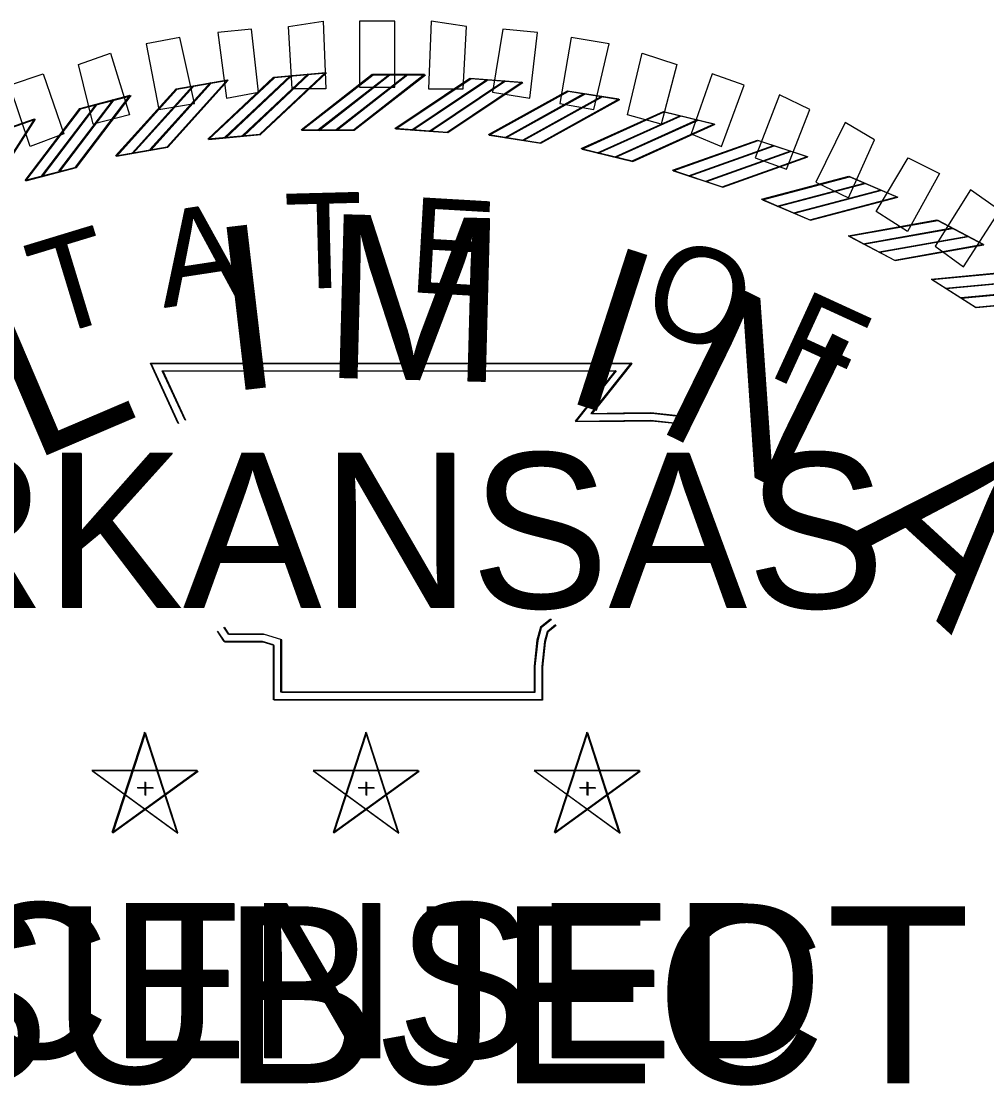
# Model space of a CAD drawing. Extents: x 16 to 1228740, y 11 to 152440.
# Drawn here: x 17.7404 to 17.8102, y 10.9139 to 10.9908 of the extents above; entities that cross this region are included whole.
import ezdxf

# ---------------------------------------------------------------- set-up
doc = ezdxf.new("R2010")
doc.units = 0
for name, color, linetype in [('STAMP_FRED', 7, 'Continuous'), ('STAMP_HUSSAM', 7, 'Continuous'), ('STAMP_JUSTIN', 7, 'Continuous'), ('STAMP_PRELIM', 7, 'Continuous')]:
    doc.layers.add(name, color=color, linetype=linetype)

msp = doc.modelspace()

# ---------------------------------------------------------------- linework, layer by layer
at = {"layer": 'STAMP_FRED'}
for p, q in [((17.758689, 10.986711), (17.762443, 10.987057)), ((17.765828, 10.986922), (17.769598, 10.986922)), ((17.77289, 10.986639), (17.776649, 10.986362)), ((17.751633, 10.985868), (17.755345, 10.986523)), ((17.74467, 10.984445), (17.748316, 10.985404)), ((17.779937, 10.985724), (17.783661, 10.985138)), ((17.737849, 10.982452), (17.741403, 10.983709)), ((17.786885, 10.98423), (17.790548, 10.983338)), ((17.760683, 10.98291), (17.764462, 10.98291)), ((17.767464, 10.983016), (17.771233, 10.982738)), ((17.753934, 10.982244), (17.757697, 10.982591)), ((17.774231, 10.982561), (17.777964, 10.981973)), ((17.793685, 10.982168), (17.797262, 10.980976)), ((17.747263, 10.981024), (17.750984, 10.98168)), ((17.780937, 10.981549), (17.784609, 10.980655)), ((17.740715, 10.979257), (17.74437, 10.980218)), ((17.787537, 10.979987), (17.791122, 10.978793)), ((17.800292, 10.97955), (17.803759, 10.978068)), ((17.793985, 10.977885), (17.797459, 10.976399)), ((17.806661, 10.976397), (17.809993, 10.974633)), ((17.800237, 10.975258), (17.803577, 10.97349)), ((17.806251, 10.972124), (17.809434, 10.970086)), ((17.749354, 10.939355), (17.746995, 10.932119)), ((17.751704, 10.932123), (17.749359, 10.939363)), ((17.765345, 10.939355), (17.762986, 10.932119)), ((17.767695, 10.932123), (17.76535, 10.939363)), ((17.781336, 10.939355), (17.778977, 10.932119)), ((17.783686, 10.932123), (17.781341, 10.939363)), ((17.753156, 10.936593), (17.745545, 10.9366)), ((17.745552, 10.936593), (17.751705, 10.932113)), ((17.747004, 10.932123), (17.753165, 10.936591)), ((17.769147, 10.936593), (17.761536, 10.9366)), ((17.761543, 10.936593), (17.767696, 10.932113)), ((17.762995, 10.932123), (17.769157, 10.936591)), ((17.785138, 10.936593), (17.777527, 10.9366)), ((17.777534, 10.936593), (17.783687, 10.932113)), ((17.778986, 10.932123), (17.785148, 10.936591)), ((17.748812, 10.935377), (17.749943, 10.935377)), ((17.749361, 10.935783), (17.749361, 10.934828)), ((17.764803, 10.935377), (17.765934, 10.935377)), ((17.765352, 10.935783), (17.765352, 10.934828)), ((17.780794, 10.935377), (17.781926, 10.935377)), ((17.781343, 10.935783), (17.781343, 10.934828))]:
    msp.add_line(p, q, dxfattribs=at)
for points in [[(17.75393, 10.982241), (17.758684, 10.986707)], [(17.755139, 10.982341), (17.759893, 10.986807)], [(17.756441, 10.98249), (17.761195, 10.986956)], [(17.757692, 10.982593), (17.762446, 10.98706)], [(17.760679, 10.982906), (17.765823, 10.986918)], [(17.761892, 10.982895), (17.767036, 10.986907)], [(17.763202, 10.982924), (17.768346, 10.986936)], [(17.764458, 10.982913), (17.769601, 10.986924)], [(17.76746, 10.983012), (17.772884, 10.986636)], [(17.747259, 10.98102), (17.751628, 10.985864)], [(17.748456, 10.98122), (17.752825, 10.986064)], [(17.749741, 10.981475), (17.754109, 10.986319)], [(17.750979, 10.981682), (17.755348, 10.986526)], [(17.768669, 10.982912), (17.774093, 10.986535)], [(17.769977, 10.982845), (17.775401, 10.986468)], [(17.771229, 10.982741), (17.776653, 10.986365)], [(17.743147, 10.979911), (17.747101, 10.9851)], [(17.744365, 10.98022), (17.748319, 10.985408)], [(17.774226, 10.982558), (17.779931, 10.985721)], [(17.775423, 10.982358), (17.781128, 10.985521)], [(17.776721, 10.982183), (17.782426, 10.985346)], [(17.77796, 10.981977), (17.783665, 10.98514)], [(17.740712, 10.979252), (17.744666, 10.984441)], [(17.741888, 10.97955), (17.745842, 10.984738)], [(17.737893, 10.978216), (17.741405, 10.983713)], [(17.780932, 10.981547), (17.786879, 10.984228)], [(17.782108, 10.981249), (17.788055, 10.98393)], [(17.783387, 10.980967), (17.789334, 10.983648)], [(17.784605, 10.980659), (17.790552, 10.98334)], [(17.787531, 10.979985), (17.793679, 10.982166)], [(17.788679, 10.979591), (17.794827, 10.981772)], [(17.789931, 10.979205), (17.796078, 10.981386)], [(17.791118, 10.978797), (17.797266, 10.980978)], [(17.793979, 10.977884), (17.800286, 10.979549)], [(17.79509, 10.977396), (17.801397, 10.979062)], [(17.796306, 10.976908), (17.802613, 10.978574)], [(17.797456, 10.976403), (17.803763, 10.978069)], [(17.800232, 10.975257), (17.806654, 10.976396)], [(17.801299, 10.97468), (17.807722, 10.975819)], [(17.80247, 10.974092), (17.808893, 10.975232)], [(17.803574, 10.973495), (17.809997, 10.974634)], [(17.806246, 10.972123), (17.812741, 10.972728)], [(17.807261, 10.971459), (17.813757, 10.972064)], [(17.80838, 10.970778), (17.814875, 10.971382)], [(17.809431, 10.970091), (17.815926, 10.970696)], [(17.751782, 10.96169), (17.749773, 10.966041), (17.784542, 10.966062), (17.781637, 10.962412), (17.783999, 10.962442), (17.785972, 10.962468), (17.787944, 10.962253)], [(17.752282, 10.96192), (17.750633, 10.965491), (17.7834, 10.96551), (17.780483, 10.961846), (17.784006, 10.961892), (17.785946, 10.961917), (17.787884, 10.961706)], [(17.778715, 10.947546), (17.777986, 10.946952), (17.777731, 10.946018), (17.777526, 10.944143), (17.777526, 10.94226), (17.759218, 10.94226), (17.759218, 10.944954), (17.759218, 10.946083), (17.757962, 10.946466), (17.755417, 10.946466), (17.755089, 10.946966)], [(17.779063, 10.947119), (17.77847, 10.946636), (17.778273, 10.945915), (17.778077, 10.944113), (17.778077, 10.941709), (17.758667, 10.941709), (17.758667, 10.944954), (17.758667, 10.945675), (17.75788, 10.945915), (17.755119, 10.945915), (17.754629, 10.946664)]]:
    msp.add_lwpolyline(points, dxfattribs=at)
at = {"layer": 'STAMP_HUSSAM'}
for p, q in [((17.758633, 10.986742), (17.762387, 10.987088)), ((17.765772, 10.986952), (17.769542, 10.986952)), ((17.772834, 10.98667), (17.776594, 10.986393)), ((17.751577, 10.985899), (17.75529, 10.986554)), ((17.744614, 10.984476), (17.74826, 10.985435)), ((17.779881, 10.985755), (17.783605, 10.985168)), ((17.786829, 10.984261), (17.790492, 10.983369)), ((17.737793, 10.982483), (17.741347, 10.98374)), ((17.760628, 10.982941), (17.764406, 10.982941)), ((17.767409, 10.983046), (17.771177, 10.982769)), ((17.753878, 10.982275), (17.757641, 10.982622)), ((17.774175, 10.982592), (17.777908, 10.982004)), ((17.79363, 10.982198), (17.797206, 10.981007)), ((17.747207, 10.981055), (17.750928, 10.981711)), ((17.780881, 10.98158), (17.784553, 10.980686)), ((17.740659, 10.979288), (17.744314, 10.980249)), ((17.787481, 10.980018), (17.791066, 10.978824)), ((17.800237, 10.979581), (17.803703, 10.978099)), ((17.793929, 10.977916), (17.797403, 10.97643)), ((17.806605, 10.976428), (17.809937, 10.974664)), ((17.800181, 10.975289), (17.803521, 10.973521)), ((17.806196, 10.972154), (17.809378, 10.970117)), ((17.749298, 10.939386), (17.746939, 10.93215)), ((17.751648, 10.932154), (17.749303, 10.939394)), ((17.765289, 10.939386), (17.76293, 10.93215)), ((17.767639, 10.932154), (17.765294, 10.939394)), ((17.78128, 10.939386), (17.778922, 10.93215)), ((17.78363, 10.932154), (17.781285, 10.939394)), ((17.7531, 10.936623), (17.745489, 10.936631)), ((17.745496, 10.936623), (17.751649, 10.932144)), ((17.746948, 10.932154), (17.75311, 10.936621)), ((17.769091, 10.936623), (17.761481, 10.936631)), ((17.761487, 10.936623), (17.76764, 10.932144)), ((17.762939, 10.932154), (17.769101, 10.936621)), ((17.785082, 10.936623), (17.777472, 10.936631)), ((17.777478, 10.936623), (17.783631, 10.932144)), ((17.77893, 10.932154), (17.785092, 10.936621)), ((17.749305, 10.935814), (17.749305, 10.934859)), ((17.765296, 10.935814), (17.765296, 10.934859)), ((17.781287, 10.935814), (17.781287, 10.934859)), ((17.748756, 10.935408), (17.749887, 10.935408)), ((17.764747, 10.935408), (17.765879, 10.935408)), ((17.780738, 10.935408), (17.78187, 10.935408))]:
    msp.add_line(p, q, dxfattribs=at)
for points in [[(17.753874, 10.982271), (17.758628, 10.986738)], [(17.755083, 10.982372), (17.759837, 10.986838)], [(17.756385, 10.982521), (17.761139, 10.986987)], [(17.757636, 10.982624), (17.76239, 10.987091)], [(17.760623, 10.982937), (17.765767, 10.986949)], [(17.761836, 10.982926), (17.76698, 10.986938)], [(17.763146, 10.982955), (17.76829, 10.986967)], [(17.764402, 10.982943), (17.769546, 10.986955)], [(17.767404, 10.983043), (17.772828, 10.986667)], [(17.768613, 10.982943), (17.774038, 10.986566)], [(17.747203, 10.981051), (17.751572, 10.985895)], [(17.7484, 10.98125), (17.752769, 10.986094)], [(17.749685, 10.981506), (17.754054, 10.98635)], [(17.750924, 10.981713), (17.755293, 10.986557)], [(17.769921, 10.982876), (17.775346, 10.986499)], [(17.771173, 10.982772), (17.776597, 10.986395)], [(17.743091, 10.979942), (17.747045, 10.98513)], [(17.744309, 10.980251), (17.748263, 10.985439)], [(17.77417, 10.982589), (17.779875, 10.985752)], [(17.775367, 10.982389), (17.781072, 10.985552)], [(17.776665, 10.982214), (17.78237, 10.985377)], [(17.777904, 10.982008), (17.783609, 10.985171)], [(17.740656, 10.979283), (17.74461, 10.984471)], [(17.741832, 10.979581), (17.745786, 10.984769)], [(17.780876, 10.981578), (17.786823, 10.984259)], [(17.737838, 10.978247), (17.74135, 10.983744)], [(17.782052, 10.98128), (17.787999, 10.983961)], [(17.783332, 10.980998), (17.789278, 10.983679)], [(17.784549, 10.98069), (17.790496, 10.983371)], [(17.787476, 10.980016), (17.793623, 10.982197)], [(17.788623, 10.979622), (17.794771, 10.981803)], [(17.789875, 10.979236), (17.796023, 10.981416)], [(17.791063, 10.978828), (17.797211, 10.981009)], [(17.793923, 10.977915), (17.80023, 10.97958)], [(17.795035, 10.977427), (17.801342, 10.979093)], [(17.79625, 10.976939), (17.802557, 10.978604)], [(17.7974, 10.976434), (17.803707, 10.9781)], [(17.800176, 10.975288), (17.806599, 10.976427)], [(17.801243, 10.97471), (17.807666, 10.97585)], [(17.802414, 10.974123), (17.808837, 10.975262)], [(17.803518, 10.973526), (17.809941, 10.974665)], [(17.80619, 10.972154), (17.812685, 10.972759)], [(17.807206, 10.97149), (17.813701, 10.972095)], [(17.808324, 10.970808), (17.814819, 10.971413)], [(17.809376, 10.970122), (17.815871, 10.970726)], [(17.751726, 10.96172), (17.749717, 10.966072), (17.784487, 10.966093), (17.781581, 10.962443), (17.783943, 10.962473), (17.785917, 10.962499), (17.787888, 10.962284)], [(17.752226, 10.961951), (17.750577, 10.965522), (17.783344, 10.965541), (17.780427, 10.961877), (17.78395, 10.961923), (17.78589, 10.961948), (17.787828, 10.961737)], [(17.77866, 10.947577), (17.77793, 10.946983), (17.777675, 10.946049), (17.77747, 10.944174), (17.77747, 10.942291), (17.759162, 10.942291), (17.759162, 10.944985), (17.759162, 10.946113), (17.757906, 10.946497), (17.755361, 10.946497), (17.755033, 10.946996)], [(17.779007, 10.94715), (17.778414, 10.946667), (17.778218, 10.945946), (17.778021, 10.944144), (17.778021, 10.94174), (17.758612, 10.94174), (17.758612, 10.944985), (17.758612, 10.945706), (17.757824, 10.945946), (17.755063, 10.945946), (17.754573, 10.946695)]]:
    msp.add_lwpolyline(points, dxfattribs=at)
at = {"layer": 'STAMP_JUSTIN'}
for p, q in [((17.758689, 10.98671), (17.762443, 10.987056)), ((17.765828, 10.98692), (17.769598, 10.98692)), ((17.772889, 10.986638), (17.776649, 10.986361)), ((17.751633, 10.985867), (17.755345, 10.986522)), ((17.74467, 10.984444), (17.748316, 10.985403)), ((17.779937, 10.985723), (17.783661, 10.985137)), ((17.737849, 10.982451), (17.741403, 10.983708)), ((17.786884, 10.984229), (17.790547, 10.983337)), ((17.760683, 10.982909), (17.764462, 10.982909)), ((17.767464, 10.983015), (17.771233, 10.982737)), ((17.753934, 10.982244), (17.757697, 10.98259)), ((17.774231, 10.98256), (17.777963, 10.981972)), ((17.793685, 10.982167), (17.797261, 10.980975)), ((17.747263, 10.981023), (17.750984, 10.981679)), ((17.780937, 10.981548), (17.784608, 10.980654)), ((17.740716, 10.979256), (17.74437, 10.980217)), ((17.787536, 10.979986), (17.791121, 10.978792)), ((17.800292, 10.97955), (17.803758, 10.978067)), ((17.793984, 10.977884), (17.797458, 10.976398)), ((17.80666, 10.976396), (17.809992, 10.974632)), ((17.800236, 10.975257), (17.803576, 10.973489)), ((17.80625, 10.972123), (17.809432, 10.970085)), ((17.749354, 10.939355), (17.746995, 10.932119)), ((17.751704, 10.932123), (17.749359, 10.939363)), ((17.765345, 10.939355), (17.762986, 10.932119)), ((17.767695, 10.932123), (17.76535, 10.939363)), ((17.781336, 10.939355), (17.778977, 10.932119)), ((17.783685, 10.932123), (17.78134, 10.939363)), ((17.753156, 10.936593), (17.745545, 10.9366)), ((17.745552, 10.936593), (17.751705, 10.932114)), ((17.747004, 10.932123), (17.753165, 10.936591)), ((17.769147, 10.936593), (17.761536, 10.9366)), ((17.761543, 10.936593), (17.767696, 10.932114)), ((17.762995, 10.932123), (17.769156, 10.936591)), ((17.785138, 10.936593), (17.777527, 10.9366)), ((17.777534, 10.936593), (17.783686, 10.932114)), ((17.778986, 10.932123), (17.785147, 10.936591)), ((17.748812, 10.935377), (17.749943, 10.935377)), ((17.749361, 10.935783), (17.749361, 10.934828)), ((17.764803, 10.935377), (17.765934, 10.935377)), ((17.765352, 10.935783), (17.765352, 10.934828)), ((17.780794, 10.935377), (17.781925, 10.935377)), ((17.781343, 10.935783), (17.781343, 10.934828))]:
    msp.add_line(p, q, dxfattribs=at)
for points in [[(17.75393, 10.98224), (17.758684, 10.986706)], [(17.755139, 10.98234), (17.759893, 10.986806)], [(17.756441, 10.982489), (17.761195, 10.986955)], [(17.757692, 10.982592), (17.762446, 10.987059)], [(17.760679, 10.982905), (17.765822, 10.986917)], [(17.761892, 10.982894), (17.767036, 10.986906)], [(17.763202, 10.982923), (17.768345, 10.986935)], [(17.764457, 10.982912), (17.769601, 10.986923)], [(17.767459, 10.983011), (17.772884, 10.986635)], [(17.747259, 10.981019), (17.751628, 10.985863)], [(17.748456, 10.981219), (17.752825, 10.986063)], [(17.749741, 10.981475), (17.75411, 10.986318)], [(17.75098, 10.981681), (17.755348, 10.986525)], [(17.768669, 10.982911), (17.774093, 10.986534)], [(17.769977, 10.982844), (17.775401, 10.986467)], [(17.771228, 10.98274), (17.776653, 10.986363)], [(17.743148, 10.97991), (17.747101, 10.985099)], [(17.744365, 10.980219), (17.748319, 10.985407)], [(17.774226, 10.982557), (17.779931, 10.98572)], [(17.775423, 10.982357), (17.781127, 10.98552)], [(17.776721, 10.982182), (17.782426, 10.985345)], [(17.777959, 10.981976), (17.783664, 10.985139)], [(17.740712, 10.979251), (17.744666, 10.98444)], [(17.741888, 10.979549), (17.745842, 10.984737)], [(17.737894, 10.978215), (17.741406, 10.983712)], [(17.780931, 10.981546), (17.786878, 10.984227)], [(17.782108, 10.981248), (17.788054, 10.983929)], [(17.783387, 10.980966), (17.789334, 10.983647)], [(17.784604, 10.980658), (17.790551, 10.983339)], [(17.787531, 10.979984), (17.793678, 10.982165)], [(17.788678, 10.97959), (17.794826, 10.981771)], [(17.78993, 10.979204), (17.796078, 10.981385)], [(17.791118, 10.978796), (17.797265, 10.980977)], [(17.793978, 10.977883), (17.800285, 10.979548)], [(17.79509, 10.977395), (17.801396, 10.979061)], [(17.796305, 10.976907), (17.802612, 10.978573)], [(17.797455, 10.976403), (17.803762, 10.978068)], [(17.800231, 10.975256), (17.806653, 10.976395)], [(17.801298, 10.974679), (17.80772, 10.975818)], [(17.802469, 10.974092), (17.808891, 10.975231)], [(17.803573, 10.973494), (17.809996, 10.974633)], [(17.806244, 10.972122), (17.812739, 10.972727)], [(17.80726, 10.971459), (17.813755, 10.972064)], [(17.808379, 10.970777), (17.814874, 10.971382)], [(17.80943, 10.97009), (17.815925, 10.970695)], [(17.751782, 10.961689), (17.749773, 10.966041), (17.784542, 10.966061), (17.781637, 10.962411), (17.783998, 10.962442), (17.785972, 10.962468), (17.787943, 10.962253)], [(17.752282, 10.96192), (17.750633, 10.965491), (17.783399, 10.96551), (17.780483, 10.961846), (17.784005, 10.961891), (17.785945, 10.961917), (17.787883, 10.961705)], [(17.778715, 10.947546), (17.777985, 10.946952), (17.77773, 10.946018), (17.777525, 10.944143), (17.777525, 10.94226), (17.759218, 10.94226), (17.759218, 10.944954), (17.759218, 10.946082), (17.757962, 10.946466), (17.755417, 10.946466), (17.755089, 10.946966)], [(17.779063, 10.947119), (17.77847, 10.946636), (17.778273, 10.945915), (17.778076, 10.944113), (17.778076, 10.941709), (17.758667, 10.941709), (17.758667, 10.944954), (17.758667, 10.945675), (17.75788, 10.945915), (17.755119, 10.945915), (17.754629, 10.946664)]]:
    msp.add_lwpolyline(points, dxfattribs=at)
at = {"layer": 'STAMP_PRELIM'}
for p, q in [((17.75971, 10.990408), (17.76221, 10.990783)), ((17.75996, 10.985908), (17.75971, 10.990408)), ((17.76221, 10.990783), (17.762402, 10.985908)), ((17.767402, 10.990783), (17.764835, 10.990783)), ((17.764835, 10.990783), (17.764835, 10.986033)), ((17.767402, 10.986033), (17.767402, 10.990783)), ((17.770027, 10.990783), (17.769835, 10.985908)), ((17.772585, 10.990408), (17.770027, 10.990783)), ((17.772335, 10.985908), (17.772585, 10.990408)), ((17.757027, 10.990224), (17.754585, 10.989974)), ((17.754585, 10.989974), (17.75521, 10.985224)), ((17.757527, 10.985658), (17.757027, 10.990224)), ((17.77521, 10.990224), (17.77446, 10.985658)), ((17.77771, 10.989974), (17.77521, 10.990224)), ((17.777152, 10.985224), (17.77771, 10.989974)), ((17.751835, 10.989599), (17.749402, 10.989158)), ((17.749402, 10.989158), (17.750335, 10.984408)), ((17.752902, 10.984849), (17.751835, 10.989599)), ((17.780152, 10.989599), (17.779335, 10.984849)), ((17.782902, 10.989158), (17.780152, 10.989599)), ((17.781777, 10.984408), (17.782902, 10.989158)), ((17.744527, 10.987658), (17.746835, 10.988474)), ((17.746835, 10.988474), (17.74821, 10.984033)), ((17.78421, 10.984033), (17.785277, 10.988474)), ((17.785277, 10.988474), (17.787777, 10.987658)), ((17.745585, 10.983349), (17.744527, 10.987658)), ((17.787777, 10.987658), (17.786652, 10.983349)), ((17.739527, 10.986158), (17.74196, 10.986974)), ((17.74196, 10.986974), (17.74346, 10.982658)), ((17.790335, 10.986974), (17.788835, 10.982658)), ((17.792652, 10.986158), (17.790335, 10.986974)), ((17.741027, 10.981724), (17.739527, 10.986158)), ((17.762402, 10.985908), (17.75996, 10.985908)), ((17.764835, 10.986033), (17.767402, 10.986033)), ((17.769835, 10.985908), (17.772335, 10.985908)), ((17.791027, 10.981724), (17.792652, 10.986158)), ((17.75521, 10.985224), (17.757527, 10.985658)), ((17.77446, 10.985658), (17.777152, 10.985224)), ((17.79521, 10.985474), (17.79346, 10.980908)), ((17.797402, 10.984408), (17.79521, 10.985474)), ((17.750335, 10.984408), (17.752902, 10.984849)), ((17.779335, 10.984849), (17.781777, 10.984408)), ((17.79571, 10.980099), (17.797402, 10.984408)), ((17.74821, 10.984033), (17.745585, 10.983349)), ((17.786652, 10.983349), (17.78421, 10.984033)), ((17.79996, 10.983474), (17.797835, 10.979158)), ((17.802085, 10.982224), (17.79996, 10.983474)), ((17.74346, 10.982658), (17.741027, 10.981724)), ((17.788835, 10.982658), (17.791027, 10.981724)), ((17.80021, 10.978033), (17.802085, 10.982224)), ((17.79346, 10.980908), (17.79571, 10.980099)), ((17.80221, 10.977033), (17.804527, 10.980908)), ((17.804527, 10.980908), (17.806777, 10.979783)), ((17.806777, 10.979783), (17.80446, 10.975599)), ((17.797835, 10.979158), (17.80021, 10.978033)), ((17.809027, 10.978599), (17.80646, 10.974533)), ((17.811152, 10.977099), (17.809027, 10.978599)), ((17.80446, 10.975599), (17.80221, 10.977033)), ((17.808527, 10.973033), (17.811152, 10.977099)), ((17.80646, 10.974533), (17.808527, 10.973033))]:
    msp.add_line(p, q, dxfattribs=at)

# ---------------------------------------------------------------- texts
at = {"layer": 'STAMP_FRED'}
for s, rotation, p in [('T', 1.47887, (17.759579, 10.971424)), ('A', 8.67877, (17.750722, 10.97006)), ('E', 356.67203, (17.768356, 10.971216)), ('T', 16.90148, (17.742394, 10.967886)), ('O', 341.2218, (17.78501, 10.968864)), ('F', 335.36282, (17.794253, 10.96525))]:
    msp.add_text(s, height=0.006859, rotation=rotation, dxfattribs=at).set_placement(p)
for s, p in [('ARKANSAS', (17.72135, 10.948369)), ('LICENSED', (17.723482, 10.915834))]:
    msp.add_text(s, height=0.0111938, dxfattribs=at).set_placement(p)
at = {"layer": 'STAMP_HUSSAM'}
for s, rotation, p in [('T', 1.47887, (17.759523, 10.971455)), ('A', 8.67877, (17.750666, 10.970091)), ('E', 356.67203, (17.768301, 10.971247)), ('T', 16.90148, (17.742339, 10.967917)), ('O', 341.2218, (17.784954, 10.968895)), ('F', 335.36282, (17.794198, 10.965281))]:
    msp.add_text(s, height=0.006859, rotation=rotation, dxfattribs=at).set_placement(p)
for s, p in [('ARKANSAS', (17.721294, 10.9484)), ('LICENSED', (17.723426, 10.915865))]:
    msp.add_text(s, height=0.0111938, dxfattribs=at).set_placement(p)
at = {"layer": 'STAMP_JUSTIN'}
for s, rotation, p in [('T', 1.47887, (17.759579, 10.971424)), ('A', 8.67877, (17.750722, 10.970059)), ('E', 356.67203, (17.768356, 10.971216)), ('T', 16.90148, (17.742395, 10.967885)), ('O', 341.2218, (17.785009, 10.968864)), ('F', 335.36282, (17.794252, 10.965249))]:
    msp.add_text(s, height=0.006859, rotation=rotation, dxfattribs=at).set_placement(p)
for s, p in [('ARKANSAS', (17.721351, 10.948369)), ('LICENSED', (17.723483, 10.915835))]:
    msp.add_text(s, height=0.0111936, dxfattribs=at).set_placement(p)
at = {"layer": 'STAMP_PRELIM'}
for s, rotation, p in [('M', 358.46666, (17.762085, 10.965033)), ('I', 6.67523, (17.755152, 10.963974)), ('I', 342.04953, (17.77921, 10.963533)), ('N', 333.84096, (17.785902, 10.961474)), ('L', 23.09236, (17.741027, 10.958908)), ('A', 317.42383, (17.799902, 10.953533))]:
    msp.add_text(s, height=0.011841, rotation=rotation, dxfattribs=at).set_placement(p)
msp.add_text('SUBJECT', height=0.0127938, dxfattribs=at).set_placement((17.731085, 10.914033))

doc.saveas('drawing.dxf')
